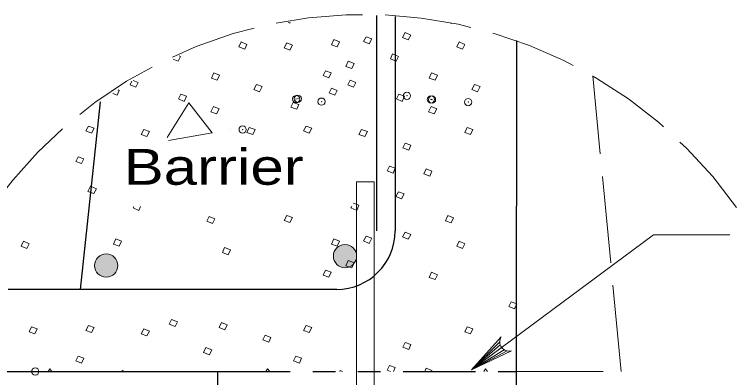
# Model space of a CAD drawing. Extents: x -1431.2 to -1397.2, y -1045.1 to -1001.1.
# Drawn here: x -1416.061 to -1412.866, y -1032.516 to -1030.908 of the extents above; entities that cross this region are included whole.
import ezdxf

# ---------------------------------------------------------------- set-up
doc = ezdxf.new("R2010")
doc.units = 0
doc.header["$LTSCALE"] = 0.064
doc.header["$PDMODE"] = 32
doc.header["$PDSIZE"] = 0.032
doc.linetypes.add('DASH_DOUBLE_DOT', pattern=[9.2, 5, -1.2, 0.3, -1.2, 0.3, -1.2])
doc.linetypes.add('LONG_DASHED', pattern=[7.5, 6, -1.5])
doc.layers.add('1', color=7, linetype='Continuous', lineweight=13)

msp = doc.modelspace()

# ---------------------------------------------------------------- hatches: boundary and pattern name
at = {"layer": '1'}
for points in [[(-1414.54716, -1031.97824, 1), (-1414.65004, -1031.97824, 1)], [(-1415.60357, -1032.0201, 1), (-1415.70646, -1032.0201, 1)]]:
    msp.add_hatch(color=256, dxfattribs=at).paths.add_polyline_path(points)

# ---------------------------------------------------------------- linework, layer by layer
at = {"layer": '1', "lineweight": 25}
for p, q in [((-1414.45917, -1030.91258), (-1414.45917, -1031.867)), ((-1414.37692, -1030.91692), (-1414.37692, -1031.867)), ((-1413.83925, -1031.02375), (-1413.84108, -1032.48925)), ((-1415.682, -1031.29517), (-1415.77025, -1032.12542)), ((-1414.63533, -1032.12542), (-1416.089, -1032.12542)), ((-1416.46242, -1032.48925), (-1415.16117, -1032.48925)), ((-1415.16117, -1033.72717), (-1415.16117, -1032.48925)), ((-1413.84108, -1032.48925), (-1413.84108, -1033.71067))]:
    msp.add_line(p, q, dxfattribs=at)
at = {"layer": '1'}
for p, q in [((-1415.28925, -1031.29942), (-1415.38458, -1031.45308)), ((-1415.10392, -1031.41775), (-1415.10383, -1031.41775)), ((-1414.54825, -1034.12175), (-1414.54825, -1031.64908)), ((-1414.46883, -1031.64908), (-1414.54825, -1031.64908)), ((-1414.46883, -1034.12175), (-1414.46883, -1031.64908)), ((-1413.91408, -1032.35783), (-1414.03958, -1032.48125)), ((-1413.91158, -1032.371), (-1414.03958, -1032.48125)), ((-1413.90575, -1032.382), (-1414.03958, -1032.48125)), ((-1413.89392, -1032.39275), (-1414.03958, -1032.48125)), ((-1413.88183, -1032.39783), (-1414.03958, -1032.48125)), ((-1415.90483, -1032.47742), (-1415.91225, -1032.48925)), ((-1415.8955, -1032.48925), (-1415.90483, -1032.47742)), ((-1415.5855, -1032.48925), (-1415.5835, -1032.485)), ((-1415.5835, -1032.485), (-1415.57333, -1032.48925)), ((-1414.94083, -1032.47742), (-1414.94833, -1032.48925)), ((-1414.93158, -1032.48925), (-1414.94083, -1032.47742)), ((-1414.62158, -1032.48925), (-1414.6195, -1032.485)), ((-1414.6195, -1032.485), (-1414.60942, -1032.48925)), ((-1414.24567, -1032.48925), (-1414.239, -1032.47433)), ((-1413.97692, -1032.47742), (-1413.98433, -1032.48925)), ((-1413.96758, -1032.48925), (-1413.97692, -1032.47742)), ((-1413.84108, -1032.48925), (-1413.84108, -1033.15717))]:
    msp.add_line(p, q, dxfattribs=at)
at = {"layer": '1', "linetype": 'DASH_DOUBLE_DOT', "lineweight": 25}
msp.add_line((-1415.16117, -1032.48925), (-1413.84108, -1032.48925), dxfattribs=at)
at = {"layer": '1'}
for points in [[(-1414.8405, -1030.94225), (-1414.84275, -1030.94633), (-1414.85, -1030.94375)], [(-1414.12867, -1030.94692), (-1414.12908, -1030.94792), (-1414.13433, -1030.946)], [(-1415.33175, -1031.09175), (-1415.3265, -1031.094), (-1415.33658, -1031.11533), (-1415.35925, -1031.10583)], [(-1415.53625, -1031.20033), (-1415.51417, -1031.20967), (-1415.52433, -1031.231), (-1415.54967, -1031.22033), (-1415.542, -1031.20408)], [(-1415.6015, -1031.24275), (-1415.597, -1031.24467), (-1415.60717, -1031.266), (-1415.62542, -1031.25833)], [(-1415.37917, -1031.46575), (-1415.18608, -1031.43183), (-1415.28925, -1031.29942)], [(-1414.56183, -1031.74392), (-1414.53667, -1031.753), (-1414.54683, -1031.77583), (-1414.57217, -1031.76517), (-1414.56875, -1031.758)], [(-1415.50283, -1031.758), (-1415.51075, -1031.77583), (-1415.53617, -1031.76517), (-1415.53275, -1031.758)], [(-1414.03958, -1032.48125), (-1413.23342, -1031.88367), (-1412.89533, -1031.88367)], [(-1413.862, -1032.3975), (-1414.03958, -1032.48125), (-1413.90783, -1032.33558)], [(-1414.39783, -1032.48925), (-1414.4115, -1032.4835), (-1414.40142, -1032.46217)], [(-1414.40142, -1032.46217), (-1414.376, -1032.47133), (-1414.38392, -1032.48925)], [(-1414.239, -1032.47433), (-1414.21367, -1032.485), (-1414.21567, -1032.48925)]]:
    msp.add_lwpolyline(points, dxfattribs=at)
for points in [[(-1414.64825, -1031.01942), (-1414.62292, -1031.03008), (-1414.63308, -1031.05142), (-1414.65842, -1031.04225)], [(-1414.5045, -1031.00725), (-1414.47917, -1031.01633), (-1414.491, -1031.03917), (-1414.51642, -1031.02858)], [(-1414.332, -1030.989), (-1414.30667, -1030.99967), (-1414.3185, -1031.02092), (-1414.34392, -1031.01033)], [(-1415.05758, -1031.03008), (-1415.03217, -1031.04075), (-1415.04233, -1031.06208), (-1415.06767, -1031.05142)], [(-1414.85633, -1031.03467), (-1414.83092, -1031.04375), (-1414.84275, -1031.06658), (-1414.86817, -1031.05592)], [(-1414.09358, -1031.03008), (-1414.06825, -1031.04075), (-1414.07833, -1031.06208), (-1414.10375, -1031.05142)], [(-1414.38783, -1031.08333), (-1414.3625, -1031.094), (-1414.37267, -1031.11533), (-1414.398, -1031.10467)], [(-1414.584, -1031.11533), (-1414.55867, -1031.126), (-1414.56883, -1031.14725), (-1414.59417, -1031.13808)], [(-1415.17933, -1031.167), (-1415.154, -1031.17767), (-1415.16408, -1031.199), (-1415.1895, -1031.18992)], [(-1414.6855, -1031.15792), (-1414.66008, -1031.167), (-1414.67025, -1031.18833), (-1414.69567, -1031.17925)], [(-1414.21533, -1031.167), (-1414.19, -1031.17767), (-1414.20017, -1031.199), (-1414.2255, -1031.18992)], [(-1414.57558, -1031.199), (-1414.55025, -1031.20967), (-1414.56033, -1031.231), (-1414.58575, -1031.22033)], [(-1414.98992, -1031.21875), (-1414.9645, -1031.22792), (-1414.97642, -1031.25075), (-1415.00175, -1031.24008)], [(-1414.65842, -1031.234), (-1414.63308, -1031.24467), (-1414.64325, -1031.266), (-1414.66858, -1031.25533)], [(-1414.02592, -1031.21875), (-1414.00058, -1031.22792), (-1414.01242, -1031.25075), (-1414.03783, -1031.24008)], [(-1415.32475, -1031.26142), (-1415.29942, -1031.2705), (-1415.3095, -1031.29333), (-1415.33492, -1031.28267)], [(-1414.36083, -1031.26142), (-1414.33542, -1031.2705), (-1414.34558, -1031.29333), (-1414.37092, -1031.28267)], [(-1414.82758, -1031.29792), (-1414.80217, -1031.30708), (-1414.81233, -1031.32833), (-1414.83775, -1031.31925)], [(-1415.181, -1031.31617), (-1415.15567, -1031.32683), (-1415.1675, -1031.34817), (-1415.19283, -1031.339)], [(-1414.21708, -1031.31617), (-1414.19167, -1031.32683), (-1414.2035, -1031.34817), (-1414.22892, -1031.339)], [(-1415.734, -1031.40292), (-1415.70867, -1031.41208), (-1415.7205, -1031.43342), (-1415.74583, -1031.42425)], [(-1414.77008, -1031.40292), (-1414.74467, -1031.41208), (-1414.7565, -1031.43342), (-1414.78192, -1031.42425)], [(-1415.48883, -1031.41817), (-1415.46342, -1031.42725), (-1415.47525, -1031.44858), (-1415.50058, -1031.4395)], [(-1415.022, -1031.409), (-1414.99667, -1031.41817), (-1415.00683, -1031.4395), (-1415.03217, -1031.43033)], [(-1414.52483, -1031.41817), (-1414.4995, -1031.42725), (-1414.51133, -1031.44858), (-1414.53667, -1031.4395)], [(-1414.05808, -1031.409), (-1414.03275, -1031.41817), (-1414.04283, -1031.4395), (-1414.06825, -1031.43033)], [(-1414.332, -1031.4775), (-1414.30667, -1031.48667), (-1414.31683, -1031.5095), (-1414.34217, -1031.49883)], [(-1415.77967, -1031.53842), (-1415.75433, -1031.5475), (-1415.76442, -1031.56883), (-1415.78983, -1031.55967)], [(-1414.40142, -1031.5795), (-1414.376, -1031.58858), (-1414.38617, -1031.61142), (-1414.4115, -1031.60075)], [(-1414.239, -1031.59167), (-1414.21367, -1031.60225), (-1414.22383, -1031.62358), (-1414.24917, -1031.6145)], [(-1415.72383, -1031.66925), (-1415.6985, -1031.67992), (-1415.71033, -1031.70125), (-1415.73567, -1031.69208)], [(-1414.3625, -1031.69358), (-1414.33708, -1031.70275), (-1414.349, -1031.72408), (-1414.37433, -1031.71492)], [(-1415.2, -1031.80225), (-1415.17458, -1031.81292), (-1415.18475, -1031.83417), (-1415.21008, -1031.8235)], [(-1414.85633, -1031.79867), (-1414.83092, -1031.80775), (-1414.84275, -1031.82908), (-1414.86817, -1031.81992)], [(-1414.14433, -1031.79867), (-1414.119, -1031.80933), (-1414.12908, -1031.83058), (-1414.1545, -1031.82142)], [(-1414.332, -1031.87167), (-1414.30667, -1031.88233), (-1414.3185, -1031.90367), (-1414.34392, -1031.893)], [(-1416.0215, -1031.91275), (-1415.99617, -1031.92342), (-1416.00625, -1031.94475), (-1416.03167, -1031.93408)], [(-1415.61225, -1031.90208), (-1415.58692, -1031.91275), (-1415.597, -1031.93408), (-1415.62242, -1031.92492)], [(-1414.64825, -1031.90208), (-1414.62292, -1031.91275), (-1414.63308, -1031.93408), (-1414.65842, -1031.92492)], [(-1414.5045, -1031.88992), (-1414.47917, -1031.89908), (-1414.491, -1031.92192), (-1414.51642, -1031.91125)], [(-1414.09358, -1031.91275), (-1414.06825, -1031.92342), (-1414.07833, -1031.94475), (-1414.10375, -1031.93408)], [(-1415.131, -1031.9405), (-1415.10558, -1031.95108), (-1415.11575, -1031.97242), (-1415.14108, -1031.96175)], [(-1414.584, -1031.998), (-1414.55867, -1032.00867), (-1414.56883, -1032.02992), (-1414.59417, -1032.02083)], [(-1414.6855, -1032.04058), (-1414.66008, -1032.04975), (-1414.67025, -1032.07108), (-1414.69567, -1032.06192)], [(-1414.21533, -1032.04975), (-1414.19, -1032.06042), (-1414.20017, -1032.08167), (-1414.2255, -1032.07258)], [(-1413.86358, -1032.18058), (-1413.83825, -1032.18975), (-1413.84842, -1032.21108), (-1413.87375, -1032.20192)], [(-1415.36558, -1032.25842), (-1415.34025, -1032.26908), (-1415.35042, -1032.29042), (-1415.37575, -1032.27975)], [(-1415.986, -1032.29175), (-1415.96058, -1032.30083), (-1415.97075, -1032.32217), (-1415.99617, -1032.313)], [(-1415.734, -1032.28567), (-1415.70867, -1032.29475), (-1415.7205, -1032.31608), (-1415.74583, -1032.30692)], [(-1415.14475, -1032.27225), (-1415.11942, -1032.28292), (-1415.1295, -1032.30425), (-1415.15492, -1032.29358)], [(-1414.77008, -1032.28567), (-1414.74467, -1032.29475), (-1414.7565, -1032.31608), (-1414.78192, -1032.30692)], [(-1414.05808, -1032.29175), (-1414.03275, -1032.30083), (-1414.04283, -1032.32217), (-1414.06825, -1032.313)], [(-1415.48883, -1032.30083), (-1415.46342, -1032.31), (-1415.47525, -1032.33133), (-1415.50058, -1032.32217)], [(-1414.9515, -1032.32758), (-1414.92617, -1032.33825), (-1414.93625, -1032.3595), (-1414.96167, -1032.34883)], [(-1414.332, -1032.36017), (-1414.30667, -1032.36933), (-1414.31683, -1032.39217), (-1414.34217, -1032.3815)], [(-1415.21375, -1032.38283), (-1415.18842, -1032.3935), (-1415.19858, -1032.41483), (-1415.22392, -1032.40417)], [(-1415.77967, -1032.42108), (-1415.75433, -1032.43017), (-1415.76442, -1032.4515), (-1415.78983, -1032.44242)], [(-1414.81575, -1032.42108), (-1414.79033, -1032.43017), (-1414.8005, -1032.4515), (-1414.82583, -1032.44242)]]:
    msp.add_lwpolyline(points, close=True, dxfattribs=at)
at = {"layer": '1', "linetype": 'LONG_DASHED'}
msp.add_lwpolyline([(-1413.84108, -1032.48925), (-1413.37642, -1032.48925), (-1413.50283, -1031.18033)], dxfattribs=at)
at = {"layer": '1'}
for centre in [(-1414.5986, -1031.97824), (-1415.65502, -1032.0201)]:
    msp.add_circle(centre, 0.05144, dxfattribs=at)
at = {"layer": '1', "linetype": 'LONG_DASHED'}
msp.add_arc((-1414.51372, -1032.92267), 2.01436, 35.13019, 188.17384, dxfattribs=at)
at = {"layer": '1', "lineweight": 25}
msp.add_arc((-1414.63534, -1031.86698), 0.25845, 270, 0, dxfattribs=at)
at = {"layer": '1'}
msp.add_arc((-1413.87243, -1032.35724), 0.04156, 148.63562, 284.46174, dxfattribs=at)
for p in [(-1414.81475, -1031.28275), (-1414.80683, -1031.2815), (-1414.32433, -1031.26842), (-1414.21833, -1031.28458), (-1414.21358, -1031.28533), (-1414.70242, -1031.29442), (-1414.05358, -1031.29633), (-1415.05142, -1031.41775), (-1415.96875, -1032.48917)]:
    msp.add_point(p, dxfattribs=at)

# ---------------------------------------------------------------- texts
at = {"layer": '1', "width": 1.25}
msp.add_text('Barrier', height=0.1588, dxfattribs=at).set_placement((-1415.5775, -1031.66233))

doc.saveas('drawing.dxf')
